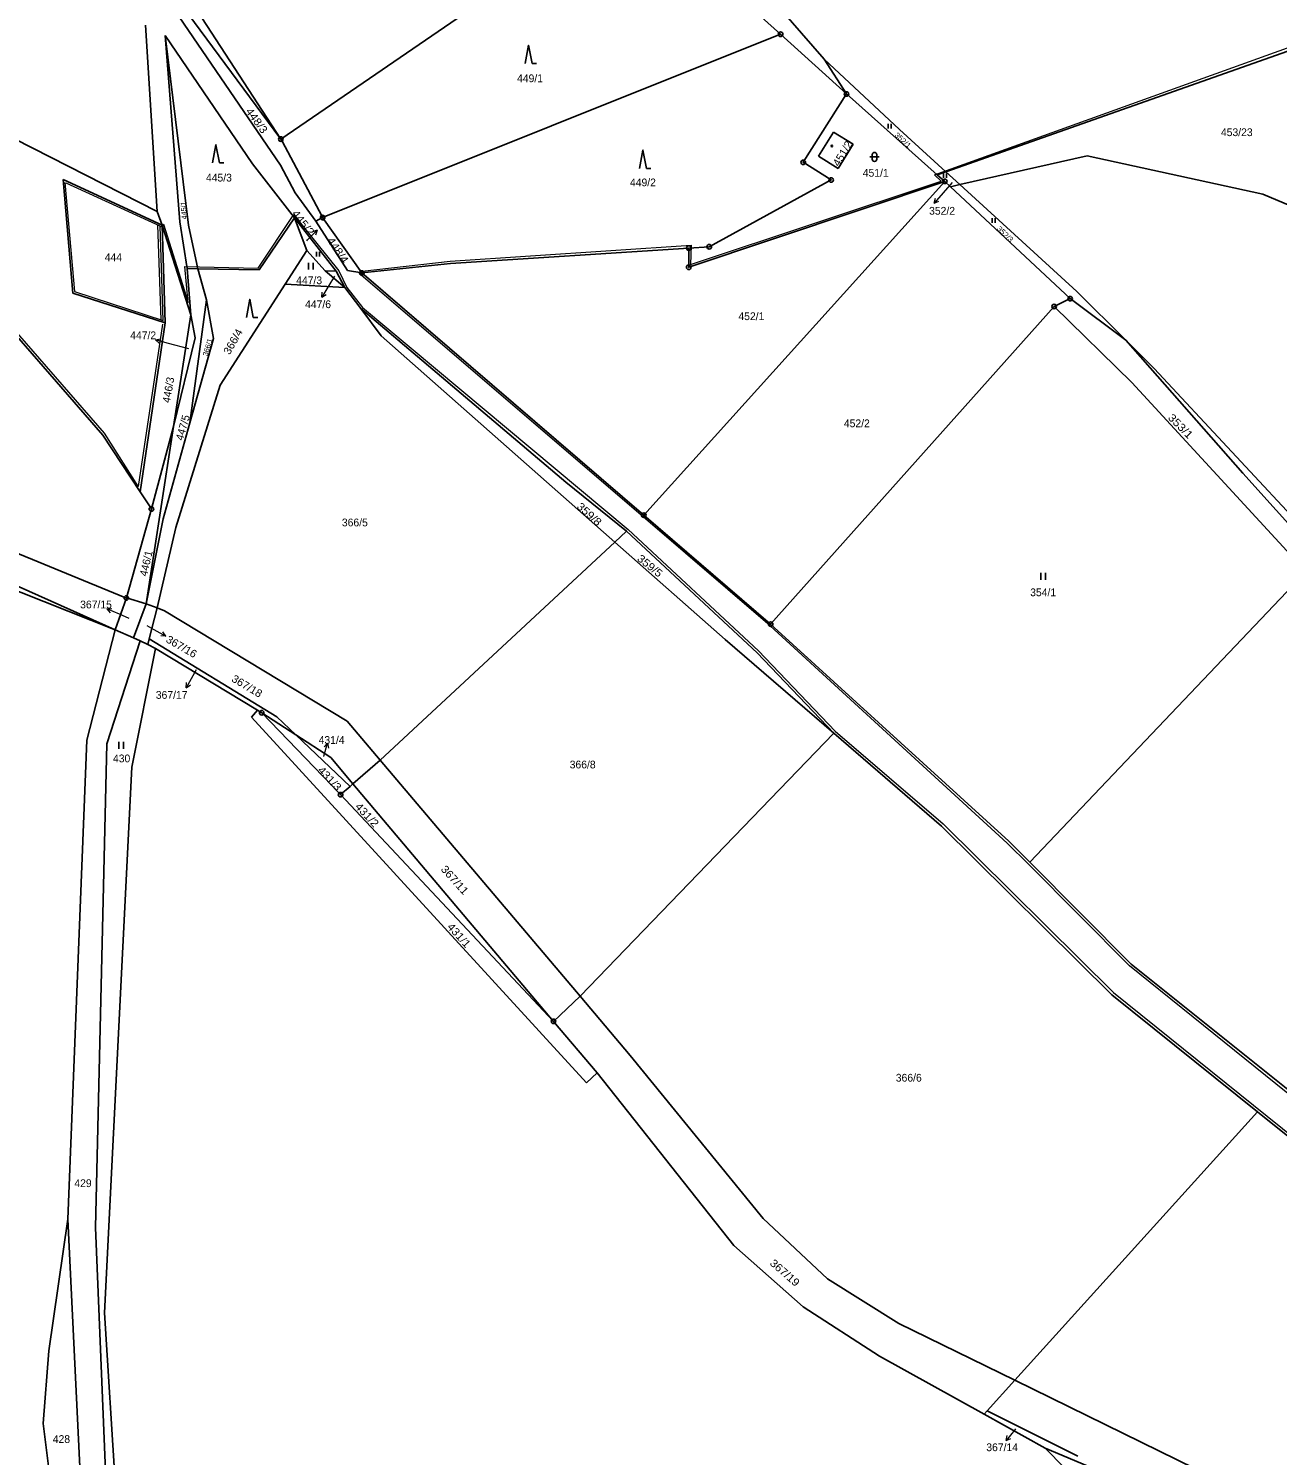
# Model space of a CAD drawing. Extents: x -633485 to -630509, y -1112692 to -1108818.
# Drawn here: x -632971.5 to -632697.5, y -1111556.4 to -1111243.4 of the extents above; entities that cross this region are included whole.
import ezdxf
from ezdxf.enums import TextEntityAlignment as Align

# ---------------------------------------------------------------- set-up
doc = ezdxf.new("R2010")
doc.units = 0
doc.header["$LTSCALE"] = 0.68
for name, color, linetype, lineweight in [('1', 7, 'Continuous', 25), ('3', 7, 'Continuous', 25), ('4', 7, 'Continuous', 13), ('5', 7, 'Continuous', 25), ('7', 7, 'Continuous', 13), ('8', 7, 'Continuous', 25)]:
    doc.layers.add(name, color=color, linetype=linetype, lineweight=lineweight)
doc.layers.add('2', color=7, linetype='Continuous')

msp = doc.modelspace()

# ---------------------------------------------------------------- linework, layer by layer
at = {"layer": '1'}
for p, q in [((-632916.13, -1111267.62), (-632839.23, -1111214.96)), ((-632948.87, -1111217.37), (-632916.13, -1111267.62)), ((-632835.97, -1111217.93), (-632806.5, -1111244.62)), ((-632814.92, -1111229.45), (-632796.95, -1111250.08)), ((-632942.9, -1111234.26), (-632916.19, -1111273.37)), ((-632942.62, -1111231.76), (-632916.13, -1111267.62)), ((-632945.83, -1111242.61), (-632943.26, -1111283.49)), ((-632941.51, -1111244.86), (-632936.37, -1111286.52)), ((-632941.51, -1111244.86), (-632922.35, -1111273.07)), ((-632941.51, -1111244.86), (-632938.3, -1111285.76)), ((-632906.96, -1111284.84), (-632806.5, -1111244.62)), ((-632806.5, -1111244.62), (-632792.05, -1111257.72)), ((-632770.24, -1111274.77), (-632691.49, -1111246.98)), ((-632796.95, -1111250.08), (-632780.39, -1111265.49)), ((-632796.95, -1111250.08), (-632792.05, -1111257.72)), ((-632990.78, -1111259.36), (-632943.26, -1111283.49)), ((-632801.52, -1111272.72), (-632792.05, -1111257.72)), ((-632792.05, -1111257.72), (-632772.11, -1111275.44)), ((-632798.16, -1111271.35), (-632794.91, -1111266.07)), ((-632794.91, -1111266.07), (-632790.55, -1111268.76)), ((-632780.39, -1111265.49), (-632770.24, -1111274.77)), ((-632916.13, -1111267.62), (-632915.86, -1111268.04)), ((-632915.86, -1111268.04), (-632907.09, -1111284.63)), ((-632793.83, -1111274.04), (-632790.55, -1111268.76)), ((-632798.16, -1111271.35), (-632793.83, -1111274.04)), ((-632767.16, -1111277.59), (-632739.26, -1111271.3)), ((-632739.26, -1111271.3), (-632700.71, -1111279.71)), ((-632922.35, -1111273.07), (-632913.13, -1111284.91)), ((-632916.19, -1111273.37), (-632912.98, -1111279.4)), ((-632801.52, -1111272.72), (-632795.4, -1111276.59)), ((-632772.11, -1111275.44), (-632770.24, -1111274.77)), ((-632772.11, -1111275.44), (-632770.46, -1111276.9)), ((-632770.24, -1111274.77), (-632767.16, -1111277.59)), ((-632963.87, -1111276.46), (-632961.8, -1111301.44)), ((-632963.87, -1111276.46), (-632942.19, -1111286.51)), ((-632836.52, -1111350.12), (-632770.46, -1111276.9)), ((-632826.65, -1111295.74), (-632770.46, -1111276.9)), ((-632822.15, -1111291.24), (-632795.4, -1111276.59)), ((-632770.46, -1111276.9), (-632769.23, -1111278.06)), ((-632769.23, -1111278.06), (-632767.16, -1111277.59)), ((-632769.23, -1111278.06), (-632742.98, -1111302.63)), ((-632767.16, -1111277.59), (-632741.49, -1111301.07)), ((-632912.98, -1111279.4), (-632908.48, -1111285.62)), ((-632700.71, -1111279.71), (-632684.32, -1111286.68)), ((-632943.26, -1111283.49), (-632942.19, -1111286.51)), ((-632920.91, -1111296.31), (-632913.13, -1111284.91)), ((-632913.13, -1111284.91), (-632904.02, -1111296.6)), ((-632913.13, -1111284.91), (-632910.44, -1111292.09)), ((-632908.48, -1111285.62), (-632906.96, -1111284.84)), ((-632907.09, -1111284.63), (-632906.96, -1111284.84)), ((-632906.96, -1111284.84), (-632898.36, -1111296.99)), ((-632942.19, -1111286.51), (-632941.51, -1111307.91)), ((-632942.19, -1111286.51), (-632935.87, -1111306.15)), ((-632938.3, -1111285.76), (-632936.68, -1111296.03)), ((-632936.37, -1111286.52), (-632934.38, -1111296.07)), ((-632908.48, -1111285.62), (-632901.52, -1111296.46)), ((-632915.16, -1111299.43), (-632910.44, -1111292.09)), ((-632910.44, -1111292.09), (-632906.43, -1111296.56)), ((-632878.93, -1111294.89), (-632826.64, -1111291.53)), ((-632826.65, -1111295.74), (-632826.64, -1111291.53)), ((-632826.64, -1111291.53), (-632822.15, -1111291.24)), ((-632936.68, -1111296.03), (-632934.38, -1111296.07)), ((-632936.68, -1111296.03), (-632935.87, -1111306.15)), ((-632934.38, -1111296.07), (-632932.42, -1111302.92)), ((-632934.38, -1111296.07), (-632920.91, -1111296.31)), ((-632906.43, -1111296.56), (-632902.13, -1111300.18)), ((-632906.43, -1111296.56), (-632904.02, -1111296.6)), ((-632904.02, -1111296.6), (-632902.13, -1111300.18)), ((-632901.52, -1111296.46), (-632898.36, -1111296.99)), ((-632898.36, -1111296.99), (-632878.93, -1111294.89)), ((-632898.36, -1111296.99), (-632836.52, -1111350.12)), ((-632929.41, -1111321.59), (-632915.16, -1111299.43)), ((-632915.16, -1111299.43), (-632902.13, -1111300.18)), ((-632902.13, -1111300.18), (-632898.62, -1111304.82)), ((-632961.8, -1111301.44), (-632941.51, -1111307.91)), ((-632936.07, -1111329.9), (-632932.42, -1111302.92)), ((-632932.42, -1111302.92), (-632930.9, -1111311.34)), ((-632746.48, -1111304.35), (-632742.98, -1111302.63)), ((-632742.98, -1111302.63), (-632730.79, -1111311.74)), ((-632741.49, -1111301.07), (-632730.79, -1111311.74)), ((-632978.8, -1111305.48), (-632955.18, -1111332.56)), ((-632939.66, -1111330.66), (-632935.87, -1111306.15)), ((-632935.87, -1111306.15), (-632934.91, -1111311.25)), ((-632898.62, -1111304.82), (-632853.63, -1111342.92)), ((-632898.62, -1111304.82), (-632894.12, -1111310.76)), ((-632808.68, -1111374.04), (-632746.48, -1111304.35)), ((-632746.48, -1111304.35), (-632729.44, -1111321)), ((-632946.98, -1111345.04), (-632941.51, -1111307.91)), ((-632939.66, -1111330.66), (-632934.91, -1111311.25)), ((-632936.07, -1111329.9), (-632930.9, -1111311.34)), ((-632894.12, -1111310.76), (-632842.85, -1111356.05)), ((-632730.79, -1111311.74), (-632724.53, -1111317.99)), ((-632730.79, -1111311.74), (-632705.09, -1111340.89)), ((-632724.53, -1111317.99), (-632688.16, -1111357)), ((-632939.18, -1111352.82), (-632929.41, -1111321.59)), ((-632729.44, -1111321), (-632692.89, -1111360.75)), ((-632945.67, -1111369.57), (-632939.66, -1111330.66)), ((-632944.53, -1111348.77), (-632939.66, -1111330.66)), ((-632941.94, -1111350.93), (-632936.07, -1111329.9)), ((-632955.18, -1111332.56), (-632946.98, -1111345.04)), ((-633029.99, -1111335.53), (-632950.39, -1111368.19)), ((-632705.09, -1111340.89), (-632688.2, -1111359.68)), ((-632853.63, -1111342.92), (-632840.27, -1111353.65)), ((-632946.98, -1111345.04), (-632944.53, -1111348.77)), ((-632950.02, -1111368.3), (-632944.53, -1111348.77)), ((-632836.52, -1111350.12), (-632808.68, -1111374.04)), ((-632945.67, -1111369.57), (-632941.94, -1111350.93)), ((-632943.27, -1111370.48), (-632939.18, -1111352.82)), ((-632842.85, -1111356.05), (-632840.27, -1111353.65)), ((-632840.27, -1111353.65), (-632811.67, -1111380.31)), ((-632894.32, -1111403.89), (-632842.85, -1111356.05)), ((-632842.85, -1111356.05), (-632818.66, -1111377.43)), ((-632996.21, -1111357.92), (-632952.49, -1111375.28)), ((-632980.47, -1111362.8), (-632952.49, -1111375.28)), ((-632751.83, -1111426.3), (-632691.24, -1111362.58)), ((-632952.49, -1111375.28), (-632950.02, -1111368.3)), ((-632950.39, -1111368.19), (-632950.02, -1111368.3)), ((-632950.02, -1111368.3), (-632945.67, -1111369.57)), ((-632948.44, -1111377.04), (-632945.67, -1111369.57)), ((-632945.67, -1111369.57), (-632943.27, -1111370.48)), ((-632945.01, -1111377.26), (-632943.27, -1111370.48)), ((-632943.27, -1111370.48), (-632941.65, -1111371.1)), ((-632941.65, -1111371.1), (-632901.58, -1111395.31)), ((-632958.68, -1111399.47), (-632952.49, -1111375.28)), ((-632952.49, -1111375.28), (-632948.44, -1111377.04)), ((-632808.68, -1111374.04), (-632756.45, -1111421.66)), ((-632954.33, -1111400.32), (-632946.99, -1111377.67)), ((-632948.44, -1111377.04), (-632946.99, -1111377.67)), ((-632946.99, -1111377.67), (-632945.34, -1111378.54)), ((-632945.34, -1111378.54), (-632945.01, -1111377.26)), ((-632945.34, -1111378.54), (-632943.66, -1111379.42)), ((-632945.01, -1111377.26), (-632917, -1111394.37)), ((-632818.66, -1111377.43), (-632794.84, -1111397.98)), ((-632948.83, -1111405.39), (-632943.66, -1111379.42)), ((-632943.66, -1111379.42), (-632921.22, -1111392.9)), ((-632811.67, -1111380.31), (-632794.84, -1111397.98)), ((-632922.58, -1111394.49), (-632921.22, -1111392.9)), ((-632922.58, -1111394.49), (-632849.08, -1111474.71)), ((-632921.22, -1111392.9), (-632920.33, -1111393.48)), ((-632920.33, -1111393.48), (-632903.03, -1111411.45)), ((-632920.33, -1111393.48), (-632912.82, -1111398.35)), ((-632917, -1111394.37), (-632912.82, -1111398.35)), ((-632901.58, -1111395.31), (-632894.32, -1111403.89)), ((-632962.9, -1111504.62), (-632958.68, -1111399.47)), ((-632956.8, -1111506.46), (-632954.33, -1111400.32)), ((-632912.82, -1111398.35), (-632900.96, -1111409.65)), ((-632912.82, -1111398.35), (-632905.19, -1111403.3)), ((-632850.5, -1111455.67), (-632794.84, -1111397.98)), ((-632794.84, -1111397.98), (-632771.19, -1111418.38)), ((-632905.19, -1111403.3), (-632900.31, -1111409.08)), ((-632900.31, -1111409.08), (-632894.32, -1111403.89)), ((-632894.32, -1111403.89), (-632850.5, -1111455.67)), ((-632954.83, -1111525.17), (-632948.83, -1111405.39)), ((-632903.03, -1111411.45), (-632900.96, -1111409.65)), ((-632900.96, -1111409.65), (-632900.31, -1111409.08)), ((-632900.31, -1111409.08), (-632856.31, -1111461.19)), ((-632903.03, -1111411.45), (-632856.31, -1111461.19)), ((-632771.19, -1111418.38), (-632733.8, -1111455.36)), ((-632756.45, -1111421.66), (-632751.83, -1111426.3)), ((-632751.83, -1111426.3), (-632729.56, -1111448.65)), ((-632729.56, -1111448.65), (-632683.44, -1111485.63)), ((-632856.31, -1111461.19), (-632850.5, -1111455.67)), ((-632850.5, -1111455.67), (-632839.49, -1111468.69)), ((-632733.8, -1111455.36), (-632701.85, -1111481.03)), ((-632856.31, -1111461.19), (-632846.75, -1111472.52)), ((-632839.49, -1111468.69), (-632810.31, -1111504.45)), ((-632849.08, -1111474.71), (-632846.75, -1111472.52)), ((-632846.75, -1111472.52), (-632816.75, -1111510.39)), ((-632755.12, -1111539.94), (-632701.85, -1111481.03)), ((-632701.85, -1111481.03), (-632690.83, -1111489.89)), ((-632967.05, -1111533.48), (-632962.9, -1111504.62)), ((-632962.9, -1111504.62), (-632955.67, -1111652.43)), ((-632956.8, -1111506.46), (-632950.83, -1111652.75)), ((-632810.31, -1111504.45), (-632796.18, -1111517.68)), ((-632816.75, -1111510.39), (-632801.51, -1111523.8)), ((-632796.18, -1111517.68), (-632780.57, -1111527.48)), ((-632954.83, -1111525.17), (-632946.63, -1111653.1)), ((-632801.51, -1111523.8), (-632784.78, -1111534.68)), ((-632780.57, -1111527.48), (-632755.12, -1111539.94)), ((-632968.26, -1111549.45), (-632967.05, -1111533.48)), ((-632784.78, -1111534.68), (-632761.85, -1111547.39)), ((-632761.16, -1111546.62), (-632755.12, -1111539.94)), ((-632755.12, -1111539.94), (-632707.54, -1111563.22)), ((-632761.85, -1111547.39), (-632761.16, -1111546.62)), ((-632761.85, -1111547.39), (-632748.42, -1111554.83)), ((-632761.16, -1111546.62), (-632741.32, -1111556.56)), ((-632968.26, -1111549.45), (-632955.67, -1111652.43)), ((-632748.42, -1111554.83), (-632724.74, -1111578.99)), ((-632748.42, -1111554.83), (-632736.49, -1111559.89))]:
    msp.add_line(p, q, dxfattribs=at)
at = {"layer": '3'}
for p, q in [((-632861.03, -1111251.04), (-632860.034, -1111251.04)), ((-632782.892, -1111265.28), (-632782.892, -1111264.275)), ((-632782.222, -1111265.28), (-632782.222, -1111264.275)), ((-632786.901, -1111271.531), (-632784.899, -1111271.531)), ((-632786.401, -1111271.031), (-632786.401, -1111272.032)), ((-632785.399, -1111272.032), (-632785.399, -1111271.031)), ((-632929.62, -1111272.86), (-632928.624, -1111272.86)), ((-632835.94, -1111274.04), (-632834.944, -1111274.04)), ((-632770.782, -1111276.14), (-632770.782, -1111275.135)), ((-632770.112, -1111276.14), (-632770.112, -1111275.135)), ((-632760.082, -1111285.99), (-632760.082, -1111284.985)), ((-632759.412, -1111285.99), (-632759.412, -1111284.985)), ((-632908.302, -1111293.36), (-632908.302, -1111292.355)), ((-632907.632, -1111293.36), (-632907.632, -1111292.355)), ((-632910.031, -1111296.24), (-632910.031, -1111294.74)), ((-632909.03, -1111296.24), (-632909.03, -1111294.74)), ((-632922.2, -1111306.75), (-632921.204, -1111306.75)), ((-632749.391, -1111364.31), (-632749.391, -1111362.81)), ((-632748.39, -1111364.31), (-632748.39, -1111362.81)), ((-632951.681, -1111401.4), (-632951.681, -1111399.9)), ((-632950.68, -1111401.4), (-632950.68, -1111399.9))]:
    msp.add_line(p, q, dxfattribs=at)
for points in [[(-632861.03, -1111251.04), (-632861.78, -1111247.04), (-632862.53, -1111251.04)], [(-632929.62, -1111272.86), (-632930.37, -1111268.86), (-632931.12, -1111272.86)], [(-632835.94, -1111274.04), (-632836.69, -1111270.04), (-632837.44, -1111274.04)], [(-632922.2, -1111306.75), (-632922.95, -1111302.75), (-632923.7, -1111306.75)]]:
    msp.add_lwpolyline(points, dxfattribs=at)
for centre, start, end in [((-632785.9, -1111271.0309), 0, 180), ((-632785.9, -1111272.0309), 180, 359.98789)]:
    msp.add_arc(centre, 0.5, start, end, dxfattribs=at)
at = {"layer": '4'}
for p, q in [((-632942.41, -1111307.31), (-632943.1, -1111286.43)), ((-632947.34, -1111343.85), (-632942, -1111308.21))]:
    msp.add_line(p, q, dxfattribs=at)
for points in [[(-632947.34, -1111343.92), (-632954.83, -1111332.11), (-632978.4, -1111305.12), (-633114.26, -1111149.3), (-633111.88, -1111145.41), (-633130.13, -1111136.51), (-633141.73, -1111154.41), (-633162, -1111176.14)], [(-632898.27, -1111296.62), (-632878.96, -1111294.41), (-632826.15, -1111290.87), (-632826.27, -1111295.11), (-632771.27, -1111276.87), (-632772.72, -1111275.47), (-632691.64, -1111246.25), (-632660.75, -1111235.05)], [(-632963.49, -1111277.11), (-632961.4, -1111301.07), (-632941.93, -1111307.41), (-632942.63, -1111286.71), (-632963.2, -1111277.29)], [(-632942.6, -1111286.95), (-632941.9, -1111286.31), (-632936.43, -1111303.46), (-632937.19, -1111295.56), (-632921.09, -1111295.91), (-632913.25, -1111284.2)], [(-632913.37, -1111284.14), (-632903.43, -1111296.53), (-632901.68, -1111300.19), (-632898.25, -1111304.55), (-632839.91, -1111353.26), (-632811.33, -1111379.91), (-632794.53, -1111397.53), (-632770.8, -1111417.89), (-632733.49, -1111454.85), (-632690.42, -1111489.51), (-632643.95, -1111526.86), (-632609.47, -1111548.69), (-632587.98, -1111560.83), (-632517.06, -1111600.62), (-632481.03, -1111616.96), (-632456.42, -1111631), (-632403.52, -1111660.86), (-632360.95, -1111682.17), (-632335.39, -1111698.14), (-632311.04, -1111711.72), (-632299.3, -1111719.74)], [(-632836.64, -1111350.53), (-632898.49, -1111297.45), (-632898.26, -1111296.69)], [(-632341.95, -1111683.59), (-632401.36, -1111655.37), (-632476.91, -1111613.68), (-632582.67, -1111558.34), (-632600.05, -1111546.02), (-632611.42, -1111539.57), (-632654.27, -1111513.39), (-632683.89, -1111486.15), (-632729.95, -1111449.04), (-632752.07, -1111426.79), (-632756.78, -1111422.08), (-632808.8, -1111374.42), (-632836.64, -1111350.53)]]:
    msp.add_lwpolyline(points, dxfattribs=at)
at = {"layer": '5'}
msp.add_circle((-632795.2468, -1111269.1192), 0.175, dxfattribs=at)
at = {"layer": '7'}
for p, q in [((-632772.779, -1111281.665), (-632771.744, -1111281.238)), ((-632908.148, -1111287.638), (-632909.21, -1111287.992)), ((-632907.166, -1111302.312), (-632906.221, -1111301.712)), ((-632943.649, -1111311.673), (-632942.811, -1111312.416)), ((-632954.312, -1111370.717), (-632953.586, -1111371.57)), ((-632941.371, -1111376.7), (-632941.988, -1111375.766)), ((-632936.895, -1111387.985), (-632935.971, -1111387.352)), ((-632905.903, -1111400.135), (-632906.66, -1111400.96)), ((-632756.978, -1111553.175), (-632755.966, -1111552.694))]:
    msp.add_line(p, q, dxfattribs=at)
for points in [[(-632768.87, -1111277.18), (-632770.81, -1111279.4), (-632772.779, -1111281.665), (-632772.5, -1111280.581)], [(-632910.43, -1111289.92), (-632910.27, -1111289.76), (-632908.148, -1111287.638), (-632908.502, -1111288.7)], [(-632904.38, -1111297.67), (-632905.62, -1111299.74), (-632907.166, -1111302.312), (-632907.079, -1111301.196)], [(-632936.32, -1111313.63), (-632940.75, -1111312.45), (-632943.649, -1111311.673), (-632942.552, -1111311.449)], [(-632949.43, -1111372.77), (-632951.55, -1111371.89), (-632954.312, -1111370.717), (-632953.195, -1111370.648)], [(-632945.52, -1111374.32), (-632943.97, -1111375.2), (-632941.371, -1111376.7), (-632942.489, -1111376.633)], [(-632934.71, -1111384.06), (-632935.44, -1111385.36), (-632936.895, -1111387.985), (-632936.847, -1111386.866)], [(-632906.76, -1111403.12), (-632906.73, -1111403.02), (-632905.903, -1111400.135), (-632905.698, -1111401.236)], [(-632754.96, -1111550.59), (-632755.13, -1111550.81), (-632756.978, -1111553.175), (-632756.756, -1111552.077)]]:
    msp.add_lwpolyline(points, dxfattribs=at)
at = {"layer": '8'}
for centre, radius in [((-632806.5, -1111244.6199), 0.5), ((-632806.5, -1111244.6199), 0.0303), ((-632792.05, -1111257.7199), 0.5), ((-632792.05, -1111257.7199), 0.0303), ((-632916.13, -1111267.6199), 0.5), ((-632916.13, -1111267.6199), 0.0303), ((-632801.52, -1111272.7199), 0.5), ((-632801.52, -1111272.7199), 0.0303), ((-632795.4, -1111276.5899), 0.5), ((-632795.4, -1111276.5899), 0.0303), ((-632770.46, -1111276.8999), 0.5), ((-632770.46, -1111276.8999), 0.0303), ((-632906.96, -1111284.8399), 0.5), ((-632906.96, -1111284.8399), 0.0303), ((-632826.64, -1111291.5299), 0.5), ((-632822.15, -1111291.2399), 0.5), ((-632826.64, -1111291.5299), 0.0303), ((-632822.15, -1111291.2399), 0.0303), ((-632898.36, -1111296.9899), 0.5), ((-632898.36, -1111296.9899), 0.0303), ((-632826.65, -1111295.7399), 0.5), ((-632826.65, -1111295.7399), 0.0303), ((-632742.98, -1111302.6299), 0.5), ((-632742.98, -1111302.6299), 0.0303), ((-632746.48, -1111304.3499), 0.5), ((-632746.48, -1111304.3499), 0.0303), ((-632944.53, -1111348.7699), 0.5), ((-632944.53, -1111348.7699), 0.0303), ((-632836.52, -1111350.1199), 0.5), ((-632836.52, -1111350.1199), 0.0303), ((-632950.02, -1111368.2999), 0.5), ((-632950.02, -1111368.2999), 0.0303), ((-632808.68, -1111374.0399), 0.5), ((-632808.68, -1111374.0399), 0.0303), ((-632920.33, -1111393.4799), 0.5), ((-632920.33, -1111393.4799), 0.0303), ((-632903.03, -1111411.4499), 0.5), ((-632903.03, -1111411.4499), 0.0303), ((-632856.31, -1111461.1899), 0.5), ((-632856.31, -1111461.1899), 0.0303)]:
    msp.add_circle(centre, radius, dxfattribs=at)

# ---------------------------------------------------------------- texts
at = {"layer": '2'}
for s, p in [('449/1', (-632864.31, -1111255.135)), ('453/23', (-632709.89, -1111266.965)), ('445/3', (-632932.56, -1111276.925)), ('451/1', (-632788.47, -1111275.875)), ('449/2', (-632839.54, -1111277.975)), ('444', (-632954.77, -1111294.405)), ('447/3', (-632912.77, -1111299.455)), ('452/1', (-632815.75, -1111307.335)), ('452/2', (-632792.61, -1111330.835)), ('366/5', (-632902.74, -1111352.585)), ('354/1', (-632751.74, -1111367.915)), ('430', (-632952.96, -1111404.355)), ('366/8', (-632852.76, -1111405.695)), ('366/6', (-632781.22, -1111474.415)), ('429', (-632961.43, -1111497.555)), ('428', (-632966.17, -1111553.695))]:
    msp.add_text(s, height=1.7, dxfattribs=at).set_placement(p)
for s, height, rotation, width, p in [('448/3', 1.7, 306, 1.1, (-632923.943, -1111261.519)), ('451/2', 1.7, 59, 1.05, (-632793.715, -1111273.788)), ('352/1', 1.139, 318, 1.1, (-632781.6, -1111266.881)), ('352/3', 1.14, 316, 1.1, (-632759.127, -1111287.415)), ('448/4', 1.7, 304, 1.1, (-632906.062, -1111289.887)), ('366/4', 1.7, 60, 1.05, (-632927.391, -1111315.072)), ('353/1', 1.7, 315, 1.15, (-632721.66, -1111328.89)), ('359/8', 1.7, 318, 1.1, (-632851.354, -1111348.455)), ('359/5', 1.7, 321, 1.1, (-632838.117, -1111359.94)), ('367/18', 1.7, 329, 1.05, (-632927.118, -1111386.484)), ('431/3', 1.7, 313, 1.1, (-632908.17, -1111406.209)), ('431/2', 1.7, 313, 1.1, (-632899.98, -1111414.199)), ('367/11', 1.7, 312, 1.1, (-632881.165, -1111427.914)), ('431/1', 1.7, 312, 1.1, (-632879.775, -1111440.554)), ('367/19', 1.7, 319, 1.1, (-632808.998, -1111514.49))]:
    msp.add_text(s, height=height, rotation=rotation, dxfattribs=dict(at, width=width)).set_placement(p)
msp.add_text('445/1', height=1.139, rotation=94, dxfattribs=at).set_placement((-632936.877, -1111283.2292), align=Align.CENTER)
for s, rotation, width, p in [('445/2', 308, 1.1, (-632911.8955, -1111286.4877)), ('367/16', 330, 1.05, (-632938.346, -1111379.7119))]:
    msp.add_text(s, height=1.7, rotation=rotation, dxfattribs=dict(at, width=width)).set_placement(p, align=Align.CENTER)
for s, p in [('352/2', (-632771.07, -1111284.205)), ('447/6', (-632907.97, -1111304.705)), ('447/2', (-632946.34, -1111311.525)), ('367/15', (-632956.68, -1111370.585)), ('367/17', (-632940.09, -1111390.425)), ('431/4', (-632905, -1111400.315)), ('367/14', (-632757.89, -1111555.495))]:
    msp.add_text(s, height=1.7, dxfattribs=at).set_placement(p, align=Align.CENTER)
for s, height, rotation, p in [('366/1', 1.139, 74, (-632932.216, -1111315.338)), ('446/3', 1.7, 80, (-632940.461, -1111325.603)), ('447/5', 1.7, 74, (-632937.621, -1111333.877)), ('446/1', 1.7, 77, (-632945.515, -1111363.665))]:
    msp.add_text(s, height=height, rotation=rotation, dxfattribs=at).set_placement(p)

doc.saveas('drawing.dxf')
